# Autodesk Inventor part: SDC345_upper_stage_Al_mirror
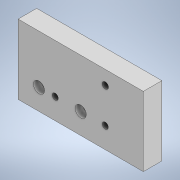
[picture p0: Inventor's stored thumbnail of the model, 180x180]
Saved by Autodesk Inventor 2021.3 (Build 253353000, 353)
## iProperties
Created: 2022-02
Part Number: SDC345_upper_stage_Al_mirror
Material: 一般
Document SubType Name: Modeling
Designer: kengo
Density: 1 g/cm^3
Appearance: 既定
Author: kengo
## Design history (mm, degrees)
derived "SDC_upper_stage_AlPlate.ipt"
feature "ソリッド1::SDC_upper_stage_AlPlate.ipt" dims "d0" = 10
tag "TaggingFeature1"
node "ソリッド1"
